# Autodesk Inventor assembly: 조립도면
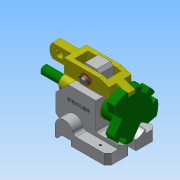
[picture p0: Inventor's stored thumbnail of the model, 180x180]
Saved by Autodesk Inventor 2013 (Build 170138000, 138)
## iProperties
Created: 2016-11
Part Number: 조립도면
Document SubType Name: Assembly
Designer: Administrator
Author: Administrator
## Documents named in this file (8)
- C:\Users\Administrator\Desktop\461108V1013\조립도면.iam
- C:\Users\Administrator\Desktop\461108V1013\본체.ipt
- C:\Users\Administrator\Desktop\461108V1013\부시.ipt
- C:\Users\Administrator\Desktop\461108V1013\분할대.ipt
- C:\Users\Administrator\Desktop\461108V1013\분할축.ipt
- C:\Users\Administrator\Desktop\461108V1013\와셔.ipt
- C:\Users\Administrator\Desktop\461108V1013\원통형핀.ipt
- C:\Users\Administrator\Desktop\461108V1013\클레비스핀.ipt
